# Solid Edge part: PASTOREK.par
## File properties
Author: Acer
Template: SEER_ExtSpurGear.par
Last saved by: Acer
Revision: 3
Application: Solid Edge
Username: Acer
Typ obsahu dokumentu: 0
Density: 7833,000 kg/m^3
Accuracy: 0,990
SEER_Parameters: SEERSG2#ER#1.609#ER#0.349065850398866#ER#0.003#ER#0.09#ER#0#ER#0.00038#ER#0#ER#5#ER#1.2#ER#0.8#ER#10000#ER#1#ER#1#ER#23#ER#37#ER#0.02#ER#0.02#ER#0.03#ER#0.03#ER#0#ER#0#ER#1000#ER#1000#ER#52.3598775598299#ER#104.71975511966#ER#9.54#ER#9.54#ER#0.92#ER#1#ER#1#ER#1#ER#1#ER#0#ER#0#ER#1#ER#0#ER#0#ER#1#ER#0#ER#0#ER#0.08#ER#0.08#ER#0.008#ER#0.008#ER#0.025#ER#0.025#ER#0#ER#1140#ER#605#ER#0#ER#1140#ER#390#ER#11#ER#SweptProtrusion_1#ER#Pattern_1#ER#SweptProtrusion_1#ER#Pattern_1#ER##ER#C:\Users\Acer\Desktop\UTB\BAKALÁŘKA\OZUBENÉ SOUKOLÍ\prevodove_kolo.par#ER#0#ER#0#ER#ExtrudedProtrusion_4#ER#ExtrudedCutout_5#ER#ExtrudedProtrusion_4#ER#ExtrudedCutout_5#ER#0#ER#0#ER#0#ER#0#ER#False#ER#0
Material: Steel
Face Style: Steel
Fill Style: ANSI32(Steel)
Virtual Style: Machined steel
Coef. of Thermal Exp: 1.3e-05
Thermal Conductivity: 32.0
Specific Heat: 481.0
Modulus of Elasticity: 199947953000.0
Poission's Ratio: 0.29
Yield Stress: 262000766.0
Ultimate Stress: 358527364.0
Elongation: 0.0
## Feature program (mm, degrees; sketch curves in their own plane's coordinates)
sketch for "unnamed Protrusion 1" plane through (0, 0, 0) normal (0, 0, 1) x-axis (1, 0, 0)
  circle centre (0, 0) radius 30.75
extrude "unnamed Protrusion 1" add finite 30 along +normal
sketch for "unnamed Cutout 1" plane through (0, 0, 30) normal (0, 0, 1) x-axis (0, 1, 0)
extrude "unnamed Cutout 1" cut through along -normal
swept protrusion "VysunutíTažením_1"
pattern "unnamed Pattern 1" of "VysunutíTažením_1"
swept protrusion "unnamed SweptProtrusion 1"
swept protrusion "unnamed SweptProtrusion 2"
swept protrusion "unnamed SweptProtrusion 3"
swept protrusion "unnamed SweptProtrusion 4"
swept protrusion "unnamed SweptProtrusion 5"
swept protrusion "unnamed SweptProtrusion 6"
swept protrusion "unnamed SweptProtrusion 7"
swept protrusion "unnamed SweptProtrusion 8"
swept protrusion "unnamed SweptProtrusion 9"
swept protrusion "unnamed SweptProtrusion 10"
swept protrusion "unnamed SweptProtrusion 11"
swept protrusion "unnamed SweptProtrusion 12"
swept protrusion "unnamed SweptProtrusion 13"
swept protrusion "unnamed SweptProtrusion 14"
swept protrusion "unnamed SweptProtrusion 15"
swept protrusion "unnamed SweptProtrusion 16"
swept protrusion "unnamed SweptProtrusion 17"
swept protrusion "unnamed SweptProtrusion 18"
swept protrusion "unnamed SweptProtrusion 19"
swept protrusion "unnamed SweptProtrusion 20"
swept protrusion "unnamed SweptProtrusion 21"
swept protrusion "unnamed SweptProtrusion 22"
sketch for "unnamed Cutout 2" plane through (0, 0.1046, 0) normal (0, 0, -1) x-axis (0, 1, 0)
  line (-2.2446, 12.6756) -> (-2.4466, 9.7219)
  line (-2.4466, 9.7219) -> (3.5394, 9.3124)
  line (3.7414, 12.2661) -> (3.5394, 9.3124)
  line (3.7414, 12.2661) -> (-2.2446, 12.6756)
extrude "unnamed Cutout 2" cut through along -normal
fillet "unnamed Round 1"
base feature "unnamed BaseFeature 1"
sketch for "Vysunutí_4" plane through (0, 0, 0) normal (0, 0, 1) x-axis (1, 0, 0)
  circle centre (0, 0) radius 34.5
extrude "Vysunutí_4" add finite 30 along +normal
sketch for "Vyříznutí_5" plane through (0, 0, 0) normal (0, 0, 1) x-axis (1, 0, 0)
  circle centre (0, 0) radius 34.5
extrude "Vyříznutí_5" cut finite 30 along +normal
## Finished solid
Body 1: sheet body, 1 face, 2 edges, 0 vertices.
  Faces by surface: cylinder 1
  Edges by curve: circle 2
Body 2: solid body, 146 faces, 432 edges, 288 vertices.
  Faces by surface: spline 115, cylinder 26, plane 5
  Edges by curve: circle 190, spline 184, intersection 44, line 14
Bounding box of the edges (mm; curved faces can reach further): 74.937 x 74.777 x 30.000, from (-37.4687, -37.2767, 0) to (37.4687, 37.5, 30).
Cylindrical faces by radius (mm): R0.4 x2, R10 x1, R30.75 x23, R34.5 x1
Planar faces by outward normal: +z 1, -z 1, oblique 3
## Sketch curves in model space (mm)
line (30.6783, 2.0984, 0) -> (12.4709, 0.853, 0)
line (12.6756, -2.14, 0) -> (9.7219, -2.342, 0)
line (9.7219, -2.342, 0) -> (9.3124, 3.644, 0)
line (12.2661, 3.846, 0) -> (9.3124, 3.644, 0)
line (12.2661, 3.846, 0) -> (12.6756, -2.14, 0)
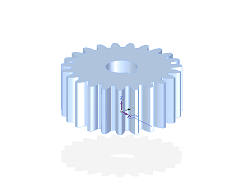
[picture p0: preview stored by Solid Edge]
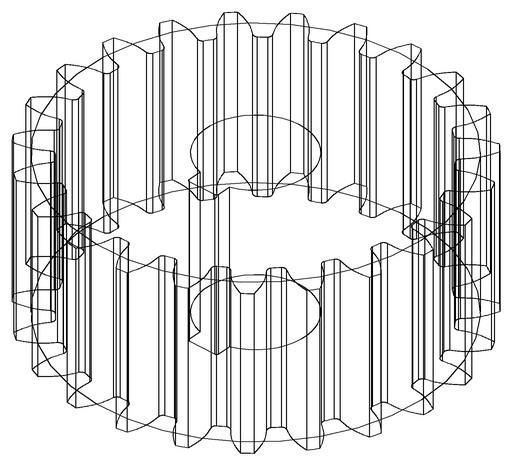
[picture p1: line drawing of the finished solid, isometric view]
